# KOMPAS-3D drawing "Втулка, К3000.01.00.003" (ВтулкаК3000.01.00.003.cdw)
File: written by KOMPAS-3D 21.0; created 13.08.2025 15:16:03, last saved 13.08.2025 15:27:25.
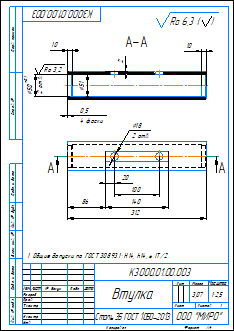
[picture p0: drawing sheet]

Sheet 1: A4, portrait

Document properties: Автор: admin; Полное имя файла: C:\Users\ShavarinML\Desktop\Стапель\2D\ВтулкаК3000.01.00.003.cdw; Знак неуказанной шероховатости: 4; Параметр неуказанной шероховатости: Ra 6,3; Масса: 3.0705

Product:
- Part/product: Втулка  | designation К3000.01.00.003
    Материал: Сталь 35 ГОСТ 1050-2013 (density 7826 kg/m3)
    Масса: 3.0705

Title block, sheet 1: Наименование: Втулка; designation: К3000.01.00.003; Материал: Сталь 35 ГОСТ 1050-2013; Масса: 3,07; Количество листов документа: 1; organisation: ООО "МИРО"; Форматы листов документа: A4

Views: Проекционный вид 2, Разрез А-А
Referenced files in C:\Users\ShavarinML\Desktop\Стапель\Из трубы\: Втулка 2.m3d
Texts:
  Ra 3,2
  Ra 6,3
  Ra 6,3 ( )
  К3000.01.00.003 Втулка
Dimensions and other numbers on the sheet: 312; 86; 20; 100; 140; 18; 2 отв.; 0,5; 4 фаски; 10; 2; 50; 51; 1:2,5; 1; 3,07

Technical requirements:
  Общие допуски по ГОСТ 30893.1: H14, h14,   IT/2.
